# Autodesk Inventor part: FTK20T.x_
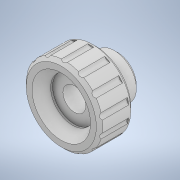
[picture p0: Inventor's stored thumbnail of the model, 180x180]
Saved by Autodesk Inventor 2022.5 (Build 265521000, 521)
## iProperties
Created: 2023-10
Part Number: FTK20T.x_
Material: 一般
Document SubType Name: Modeling
Designer: ImaoCorp
Density: 1 g/cm^3
Appearance: 既定
Sending System: SOLIDWORKS 2021-2021301
MC: AMD64
MC_MODEL: Intel64 Family 6 Model 60 Stepping 3, GenuineIntel
OS: Windows_NT
FRU: Parasolid Version 32.1, build 255,  1- 1-2021
FORMAT: text
GUISE: transmit
KEY: FTK20T
FILE: FTK20T.x_t
DATE: Tue Oct 17 11:07:29 2023
Author: ImaoCorp
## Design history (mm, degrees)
feature "Base1"
node "ソリッド1"
